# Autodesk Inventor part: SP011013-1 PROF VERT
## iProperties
Created: 2013-01
Part Number: SP011013-1 PROF VERT
Material: Aluminum-6061
Description: PROFILE 45X45 UL
Document SubType Name: Modeling
Designer: Administrator
Stock Number: 20.1063 PROFILE 45X45 UL
Density: 2.71 g/cm^3
Mass: 1462.47 g
Surface Area: 6404.2 cm^2
Volume: 539.657 cm^3
FINISH: CLEAR ANODIZED
Author: Administrator
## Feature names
1. Extrusion1
